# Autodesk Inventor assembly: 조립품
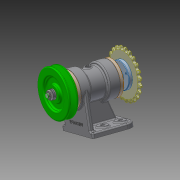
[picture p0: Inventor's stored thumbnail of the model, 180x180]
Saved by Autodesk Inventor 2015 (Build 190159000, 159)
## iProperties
Created: 2024-02
Part Number: 조립품
Document SubType Name: Assembly
Designer: 10420
Author: 10420
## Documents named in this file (18)
- C:\Users\10420\Desktop\740204V1012\조립품.iam
- C:\Users\10420\Desktop\740204V1012\본체.ipt
- C:\Users\10420\Desktop\740204V1012\V-벨트풀리.ipt
- C:\Users\10420\Desktop\740204V1012\스프로킷.ipt
- C:\Users\10420\Desktop\740204V1012\스프링 와셔 M10.ipt
- C:\Users\10420\Desktop\740204V1012\앤드 캡.ipt
- C:\Users\10420\Desktop\740204V1012\가스켓.ipt
- C:\Users\10420\Desktop\740204V1012\깊은 홈 볼 베어링 6204.ipt
- C:\Users\10420\Desktop\740204V1012\오일 실 20 32 5.ipt
- C:\Users\10420\Desktop\740204V1012\육각 너트 M10x1.ipt
- C:\Users\10420\Desktop\740204V1012\축.ipt
- C:\Users\10420\Desktop\740204V1012\커버.ipt
- C:\Users\10420\Desktop\740204V1012\평와셔 M10.ipt
- C:\Users\10420\Desktop\740204V1012\평행 키 5x5x12.ipt
- C:\Users\10420\Desktop\740204V1012\플랜지.ipt
- C:\Users\10420\Desktop\740204V1012\스프링 와셔 M5.ipt
- C:\Users\10420\Desktop\740204V1012\육각 소켓 머리 볼트 M5 x 12.ipt
- C:\Users\10420\Desktop\740204V1012\육각 소켓 머리 볼트 M4 x 10.ipt
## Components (4 placed, 3 different names)
1. V-벨트풀리:1
2. 가스켓:1
3. 가스켓:2
4. 플랜지:1
